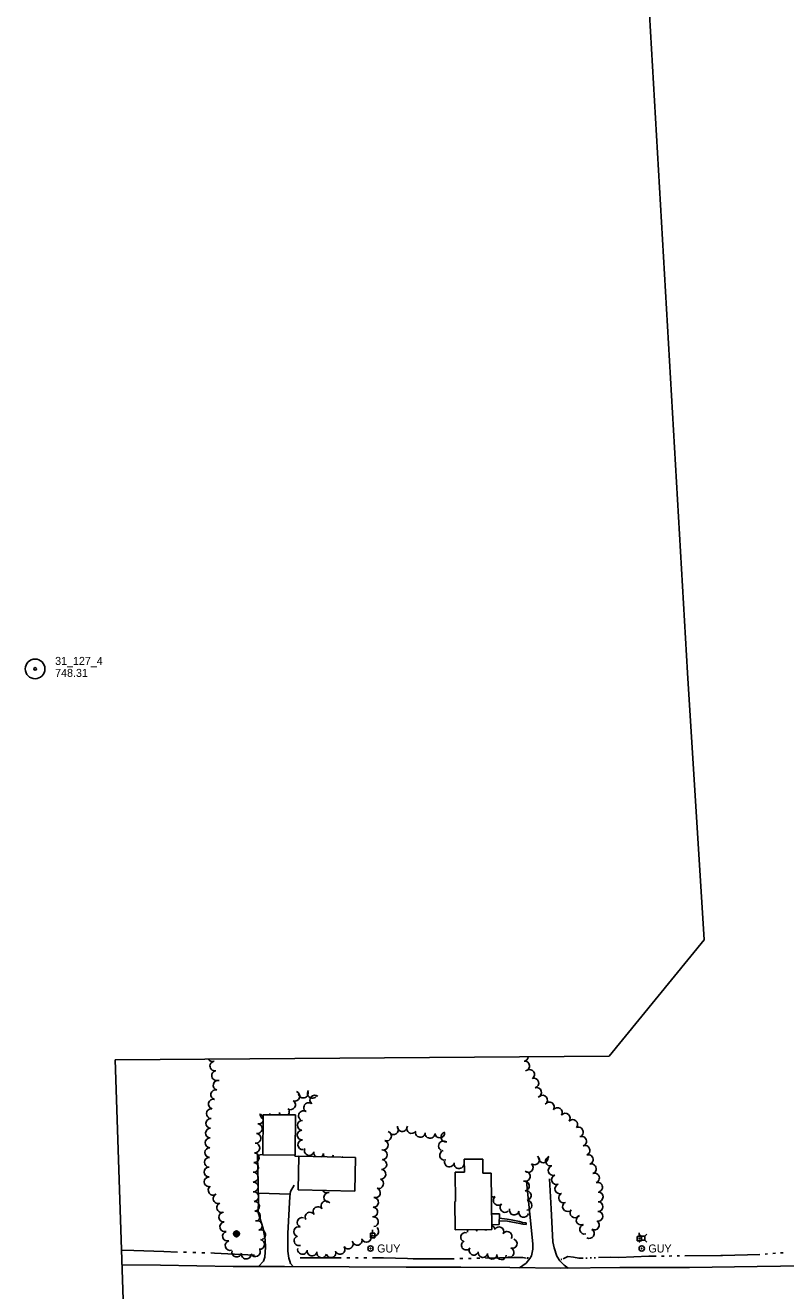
# Model space of a CAD drawing. Extents: x 589250 to 1188077, y 162953 to 363065.
# Drawn here: x 593418 to 593989, y 170392 to 171341 of the extents above; entities that cross this region are included whole.
import ezdxf

# ---------------------------------------------------------------- set-up
doc = ezdxf.new("R2010")
doc.units = 0
for name, color, linetype in [('E_BLD', 7, 'Continuous'), ('E_BLD_HvyDash', 7, 'Continuous'), ('E_DRN', 7, 'Continuous'), ('E_DWY', 7, 'Continuous'), ('E_LAND_TreeLine_P', 7, 'Continuous'), ('E_MAP_Limits', 7, 'Continuous'), ('E_MAP_PassPoints', 7, 'Continuous'), ('E_MISCPROP', 7, 'Continuous'), ('E_PATH_Sidewalk', 7, 'Continuous'), ('E_RDWY', 7, 'Continuous'), ('E_UTL_AG_Bold', 7, 'Continuous'), ('E_UTL_EGuyWire', 7, 'Continuous'), ('E_UTL_EPowerPole', 7, 'Continuous'), ('E_WTR_FlowLine', 7, 'Continuous')]:
    doc.layers.add(name, color=color, linetype=linetype)

msp = doc.modelspace()

# ---------------------------------------------------------------- linework, layer by layer
at = {"layer": 'E_BLD'}
for p, q in [((593596.59, 170524.31), (593596.3, 170494.1)), ((593620.91, 170524.08), (593596.59, 170524.31)), ((593620.62, 170493.87), (593620.91, 170524.08)), ((593596.3, 170494.1), (593620.62, 170493.87)), ((593622.87, 170467.85), (593623.47, 170493.12)), ((593623.47, 170493.12), (593665.84, 170492.11)), ((593665.84, 170492.11), (593665.24, 170466.84)), ((593747.47, 170490.87), (593761.25, 170491.02)), ((593747.58, 170481.31), (593747.47, 170490.87)), ((593761.25, 170491.02), (593761.36, 170480.45)), ((593740.62, 170481.23), (593747.58, 170481.31)), ((593740.87, 170459.14), (593740.62, 170481.23)), ((593761.36, 170480.45), (593767.6, 170480.52)), ((593767.6, 170480.52), (593768.07, 170438.24)), ((593665.24, 170466.84), (593622.87, 170467.85)), ((593740.48, 170459.14), (593740.87, 170459.14)), ((593740.71, 170437.93), (593740.48, 170459.14)), ((593768.07, 170438.24), (593740.71, 170437.93))]:
    msp.add_line(p, q, dxfattribs=at)
at = {"layer": 'E_BLD_HvyDash'}
for p, q in [((593773.77, 170449.92), (593767.94, 170450.05)), ((593773.65, 170441.94), (593773.77, 170449.92)), ((593768.03, 170441.78), (593773.65, 170441.94))]:
    msp.add_line(p, q, dxfattribs=at)
at = {"layer": 'E_DRN'}
for centre, radius, start, end in [((593794.38, 170417.05), 0.781, 280.48427, 26.74447), ((593820.6, 170415.98), 0.391, 153.61437, 259.87457)]:
    msp.add_arc(centre, radius, start, end, dxfattribs=at)
at = {"layer": 'E_DWY'}
for p, q in [((593592.33, 170494.01), (593596.3, 170494.4)), ((593593.14, 170460.32), (593592.33, 170494.01)), ((593620.11, 170493.87), (593620.58, 170493.26)), ((593620.58, 170493.26), (593623.47, 170493.01)), ((593796.71, 170449.6), (593794.02, 170474.12)), ((593811.44, 170476.21), (593812.67, 170453.71)), ((593593.02, 170465.45), (593616.88, 170464.81)), ((593617.17, 170466.68), (593616.62, 170463.05)), ((593619.81, 170471.44), (593617.17, 170466.68)), ((593592.89, 170450.95), (593593.14, 170460.32)), ((593616.62, 170463.05), (593615.17, 170435.08)), ((593596.56, 170438.94), (593592.89, 170450.95)), ((593798.96, 170427.37), (593796.71, 170449.6)), ((593812.67, 170453.71), (593813.91, 170428.89)), ((593597.99, 170430.55), (593596.56, 170438.94)), ((593615.17, 170435.08), (593615.07, 170421.94)), ((593598.42, 170424.96), (593597.99, 170430.55)), ((593798.97, 170423.41), (593798.96, 170427.37)), ((593813.91, 170428.89), (593814.79, 170424.39)), ((593596.78, 170414.33), (593597.89, 170417.55)), ((593597.89, 170417.55), (593598.42, 170424.96)), ((593615.07, 170421.94), (593615.78, 170416.63)), ((593615.78, 170416.63), (593616.49, 170414.53)), ((593793.92, 170412.94), (593796.67, 170416.43)), ((593796.67, 170416.43), (593797.83, 170418.47)), ((593797.83, 170418.47), (593798.97, 170423.41)), ((593814.79, 170424.39), (593816.85, 170418.3)), ((593816.85, 170418.3), (593819.18, 170414.68)), ((593593.15, 170410.46), (593596.78, 170414.33)), ((593616.49, 170414.53), (593617.2, 170412.58)), ((593617.2, 170412.58), (593619.02, 170410.38)), ((593788.85, 170409.54), (593793.92, 170412.94)), ((593819.18, 170414.68), (593822.38, 170411.49)), ((593822.38, 170411.49), (593825.44, 170409.26))]:
    msp.add_line(p, q, dxfattribs=at)
at = {"layer": 'E_LAND_TreeLine_P'}
for centre, radius, start, end in [((593558.53, 170567.82), 3.65, 210.62005, 292.17055), ((593560.34, 170560.77), 3.65, 100.38339, 280.38339), ((593791.82, 170568.04), 3.65, 277.67528, 353.96501), ((593792.8, 170560.8), 3.65, 277.67528, 97.67528), ((593561.66, 170553.58), 3.65, 100.38339, 280.38339), ((593562.76, 170546.4), 3.65, 75.64496, 255.64496), ((593796.44, 170554.51), 3.65, 301.78692, 121.78692), ((593799.64, 170548), 3.65, 286.68378, 106.68378), ((593560.94, 170539.31), 3.65, 75.64496, 255.64496), ((593620.34, 170538.16), 3.65, 251.74447, 71.74447), ((593626.74, 170540.47), 3.65, 191.48935, 11.48935), ((593633.51, 170540.23), 3.65, 142.02219, 322.02219), ((593801.74, 170541), 3.65, 286.68378, 106.68378), ((593559.13, 170532.23), 3.65, 75.64496, 255.64496), ((593617.15, 170531.65), 3.65, 236.48935, 56.48935), ((593630.72, 170529.65), 3.65, 57.15555, 237.15555), ((593635.34, 170535.32), 3.65, 50.07851, 230.07851), ((593806.14, 170535.2), 3.65, 308.5469, 128.5469), ((593811.24, 170530.07), 3.65, 325.40159, 145.40159), ((593557.36, 170517.8), 3.65, 87.6533, 267.6533), ((593557.66, 170525.1), 3.65, 87.6533, 267.6533), ((593593.3, 170521.07), 3.65, 26.57538, 79.39512), ((593597.95, 170524.69), 3.65, 186.25188, 247.51465), ((593597.95, 170524.69), 3.65, 353.28171, 6.25188), ((593605.22, 170525.49), 3.65, 186.25188, 199.59145), ((593605.22, 170525.49), 3.65, 339.31894, 6.25188), ((593612.45, 170526.47), 3.65, 196.12482, 218.57161), ((593612.45, 170526.47), 3.65, 320.33879, 16.12482), ((593626.76, 170523.51), 3.65, 57.15555, 237.15555), ((593817.26, 170525.92), 3.65, 325.40159, 145.40159), ((593823.22, 170521.7), 3.65, 320.14916, 140.14916), ((593828.83, 170517.01), 3.65, 320.14916, 140.14916), ((593557.06, 170510.49), 3.65, 87.6533, 267.6533), ((593592.12, 170513.86), 3.65, 263.0544, 83.0544), ((593593.3, 170521.07), 3.65, 259.39512, 332.33501), ((593625.78, 170509.04), 3.65, 93.87081, 273.87081), ((593625.93, 170516.34), 3.65, 86.48803, 266.48803), ((593689.16, 170508.32), 3.65, 250.5256, 70.5256), ((593694.37, 170513.03), 3.65, 213.29076, 33.29076), ((593700.88, 170515.3), 3.65, 172.74801, 352.74801), ((593707.97, 170513.89), 3.65, 149.21566, 329.21566), ((593714.52, 170511), 3.65, 174.46883, 354.46883), ((593733.67, 170507.57), 3.65, 101.48935, 281.48935), ((593832.97, 170511.29), 3.65, 290.08317, 110.08317), ((593556.76, 170503.19), 3.65, 87.6533, 267.6533), ((593590.46, 170499.34), 3.65, 265.86339, 85.86339), ((593591.23, 170506.61), 3.65, 263.0544, 83.0544), ((593626.27, 170501.75), 3.65, 93.87081, 273.87081), ((593686.72, 170501.42), 3.65, 250.5256, 70.5256), ((593721.8, 170510.29), 3.65, 174.46883, 354.46883), ((593729.08, 170510.56), 3.65, 184.75334, 4.75334), ((593731.8, 170500.89), 3.65, 62.10693, 242.10693), ((593835.48, 170504.43), 3.65, 290.08317, 110.08317), ((593556.18, 170488.58), 3.65, 87.74277, 267.74277), ((593556.47, 170495.88), 3.65, 87.74277, 267.74277), ((593589.93, 170492.05), 3.65, 265.86339, 85.86339), ((593631.15, 170497.39), 3.65, 153.61437, 333.61437), ((593638.24, 170495.8), 3.65, 170.49063, 234.65458), ((593638.24, 170495.8), 3.65, 302.62182, 350.49063), ((593645.45, 170494.59), 3.65, 170.49063, 211.71243), ((593645.45, 170494.59), 3.65, 325.56397, 350.49063), ((593652.66, 170493.4), 3.65, 170.7171, 194.16346), ((593652.66, 170493.4), 3.65, 343.11294, 350.7171), ((593686.07, 170494.23), 3.65, 270.17942, 90.17942), ((593732.63, 170493.92), 3.65, 104.21566, 284.21566), ((593800.14, 170490.33), 3.65, 230.37385, 50.37385), ((593806.8, 170491.94), 3.65, 182.30052, 2.30052), ((593812.1, 170489.47), 3.65, 105.82167, 285.82167), ((593837.99, 170497.56), 3.65, 290.08317, 110.08317), ((593840.44, 170490.67), 3.65, 288.61437, 108.61437), ((593556, 170481.27), 3.65, 90.17942, 270.17942), ((593589.4, 170484.76), 3.65, 265.86339, 85.86339), ((593684.94, 170479.66), 3.65, 264.60722, 84.60722), ((593685.63, 170486.94), 3.65, 264.60722, 84.60722), ((593736.28, 170488.82), 3.65, 169.68794, 349.68794), ((593743.47, 170487.51), 3.65, 169.68794, 349.68794), ((593750.7, 170486.42), 3.65, 171.56377, 210.00969), ((593795.48, 170484.7), 3.65, 230.37385, 50.37385), ((593814.12, 170482.44), 3.65, 109.92626, 289.92626), ((593842.78, 170483.75), 3.65, 288.61437, 108.61437), ((593556.03, 170473.96), 3.65, 90.17942, 270.17942), ((593589.2, 170477.46), 3.65, 270.17942, 90.17942), ((593589.22, 170470.15), 3.65, 270.17942, 90.17942), ((593683.27, 170472.6), 3.65, 250.3242, 70.3242), ((593792.48, 170470.77), 3.65, 281.48935, 101.48935), ((593793.26, 170478.02), 3.65, 262.82704, 82.82704), ((593816.61, 170475.57), 3.65, 109.92626, 289.92626), ((593845.11, 170476.82), 3.65, 288.61437, 108.61437), ((593847.45, 170469.89), 3.65, 288.61437, 108.61437), ((593559.06, 170467.61), 3.65, 125.00391, 305.00391), ((593562.83, 170461.39), 3.65, 111.98083, 291.98083), ((593589.51, 170462.85), 3.65, 275.02342, 95.02342), ((593644.35, 170469.37), 3.65, 212.37985, 287.28215), ((593645.8, 170462.3), 3.65, 87.16663, 267.16663), ((593680.81, 170465.72), 3.65, 250.3242, 70.3242), ((593793.94, 170463.6), 3.65, 281.48935, 101.48935), ((593819.1, 170468.7), 3.65, 109.92626, 289.92626), ((593821.89, 170461.94), 3.65, 112.55955, 292.55955), ((593847.88, 170462.66), 3.65, 269.22458, 89.22458), ((593565.56, 170454.61), 3.65, 111.98083, 291.98083), ((593590.15, 170455.57), 3.65, 275.02342, 95.02342), ((593637.76, 170451.66), 3.65, 35.88611, 215.88611), ((593643.68, 170455.95), 3.65, 35.88611, 215.88611), ((593678.84, 170451.31), 3.65, 265.13697, 85.13697), ((593679.46, 170458.59), 3.65, 265.13697, 85.13697), ((593769.17, 170466.19), 3.65, 247.86032, 294.52051), ((593772.89, 170460), 3.65, 133.71062, 313.71062), ((593777.94, 170454.72), 3.65, 133.71062, 313.71062), ((593794.51, 170456.37), 3.65, 267.45311, 87.45311), ((593824.87, 170455.32), 3.65, 139.94306, 319.94306), ((593847.78, 170455.35), 3.65, 269.22458, 89.22458), ((593567, 170447.51), 3.65, 95.70696, 275.70696), ((593590.79, 170448.28), 3.65, 275.02342, 95.02342), ((593592.21, 170441.17), 3.65, 289.83324, 109.83324), ((593625.72, 170443.5), 3.65, 69.85628, 249.85628), ((593631.75, 170447.51), 3.65, 31.9389, 211.9389), ((593679.31, 170444.03), 3.65, 275.07851, 95.07851), ((593784.9, 170452.73), 3.65, 166.14318, 346.14318), ((593792, 170450.98), 3.65, 166.14318, 346.14318), ((593830.47, 170450.62), 3.65, 139.94306, 319.94306), ((593835.11, 170445.22), 3.65, 111.55004, 291.55004), ((593844.98, 170441.47), 3.65, 239.4797, 59.4797), ((593847.68, 170448.05), 3.65, 269.22458, 89.22458), ((593567.8, 170440.25), 3.65, 105.77223, 285.77223), ((593569.79, 170433.21), 3.65, 105.77223, 285.77223), ((593594.69, 170434.3), 3.65, 289.83324, 109.83324), ((593623.2, 170436.64), 3.65, 69.85628, 249.85628), ((593679.56, 170436.88), 3.65, 227.90573, 47.90573), ((593748.27, 170432.4), 3.52, 75.248, 255.248), ((593753.29, 170436.55), 3.52, 155.03675, 185.37385), ((593753.29, 170436.55), 3.52, 5.37385, 26.23806), ((593760.29, 170437.21), 3.52, 165.15537, 185.37385), ((593766.92, 170437.92), 3.52, 175.65971, 186.18843), ((593760.29, 170437.21), 3.52, 5.37385, 16.11944), ((593766.92, 170437.92), 3.52, 6.18843, 71.54959), ((593773.54, 170436.7), 3.52, 332.10693, 152.10693), ((593779.63, 170433.19), 3.52, 328.57192, 148.57192), ((593837.73, 170438.41), 3.65, 104.21566, 284.21566), ((593841.27, 170435.17), 3.65, 239.4797, 59.4797), ((593571.78, 170426.18), 3.65, 105.77223, 285.77223), ((593594.04, 170427.09), 3.65, 262.32611, 82.32611), ((593623.45, 170429.72), 3.65, 107.99831, 287.99831), ((593660.41, 170427.33), 3.65, 213.29076, 33.29076), ((593667.12, 170430.05), 3.65, 196.68378, 16.68378), ((593674.07, 170432.3), 3.65, 201.98083, 21.98083), ((593748.8, 170426.35), 3.52, 140.37385, 320.37385), ((593783.49, 170427.63), 3.52, 251.00041, 71.00041), ((593576.81, 170421.27), 3.65, 166.9389, 346.9389), ((593583.95, 170419.74), 3.65, 174.46883, 354.46883), ((593590.77, 170421.48), 3.65, 206.74447, 26.74447), ((593626.09, 170423.22), 3.65, 170.45184, 350.45184), ((593633.3, 170422), 3.65, 170.45184, 350.45184), ((593640.48, 170420.65), 3.65, 166.14318, 346.14318), ((593647.48, 170420.71), 3.65, 199.9783, 19.9783), ((593654.3, 170423.31), 3.65, 213.29076, 33.29076), ((593754.67, 170422.48), 3.52, 147.27418, 327.27418), ((593761.42, 170420.76), 3.52, 169.22536, 349.22536), ((593768.35, 170419.58), 3.52, 176.0938, 356.0938), ((593775.37, 170419.1), 3.52, 176.0938, 356.0938), ((593781.2, 170420.97), 3.52, 251.00041, 71.00041)]:
    msp.add_arc(centre, radius, start, end, dxfattribs=at)
at = {"layer": 'E_MAP_Limits'}
for p, q in [((593914.91, 170855.75), (593880.25, 171456.06)), ((593927.49, 170655.35), (593914.91, 170855.75)), ((593856.11, 170568.09), (593927.49, 170655.35)), ((593485.69, 170565.46), (593856.11, 170568.09)), ((593496.33, 170239.23), (593485.69, 170565.46))]:
    msp.add_line(p, q, dxfattribs=at)
at = {"layer": 'E_MAP_PassPoints'}
for radius in [7.38, 7.38, 0.945, 0.945]:
    msp.add_circle((593425.57, 170858.64), radius, dxfattribs=at)
at = {"layer": 'E_MISCPROP'}
for radius in [2.23, 1.67, 1.12, 0.558]:
    msp.add_circle((593576.62, 170434.92), radius, dxfattribs=at)
at = {"layer": 'E_PATH_Sidewalk'}
for p, q in [((593773.69, 170444.8), (593779.81, 170444.52)), ((593773.72, 170446.61), (593779.66, 170446.03)), ((593779.66, 170446.03), (593782.52, 170445.44)), ((593782.52, 170445.44), (593788.85, 170444.1)), ((593779.81, 170444.52), (593783.73, 170443.78)), ((593783.73, 170443.78), (593787.95, 170442.89)), ((593787.95, 170442.89), (593791.26, 170442.15)), ((593788.85, 170444.1), (593791.11, 170443.5)), ((593791.11, 170443.5), (593793.97, 170443.21)), ((593791.26, 170442.15), (593793.97, 170441.86)), ((593793.97, 170443.21), (593793.97, 170441.86))]:
    msp.add_line(p, q, dxfattribs=at)
at = {"layer": 'E_RDWY'}
for p, q in [((593490.7, 170411.78), (593519.56, 170411.41)), ((593519.56, 170411.41), (593573.99, 170410.53)), ((593573.99, 170410.53), (593612.72, 170410.39)), ((593612.72, 170410.39), (593661.14, 170410.28)), ((593661.14, 170410.28), (593703.79, 170409.89)), ((593703.79, 170409.89), (593744.88, 170410.02)), ((593744.88, 170410.02), (593781.51, 170409.61)), ((593781.51, 170409.61), (593819.98, 170409.21)), ((593819.98, 170409.21), (593864.16, 170409.61)), ((593916.35, 170409.77), (593864.16, 170409.61)), ((593967.14, 170410.4), (593916.35, 170409.77)), ((594002.09, 170410.98), (593967.14, 170410.4))]:
    msp.add_line(p, q, dxfattribs=at)
at = {"layer": 'E_UTL_AG_Bold'}
for points in [[(593880.04, 170433.12), (593878.44, 170434.71)], [(593880.04, 170430.31), (593878.44, 170428.71)], [(593882.85, 170433.12), (593884.44, 170434.71)], [(593882.85, 170430.31), (593884.44, 170428.71)]]:
    msp.add_lwpolyline(points, dxfattribs=at)
msp.add_lwpolyline([(593880.04, 170430.31), (593882.85, 170430.31), (593882.85, 170433.12), (593880.04, 170433.12)], close=True, dxfattribs=at)
at = {"layer": 'E_UTL_EGuyWire'}
for centre, radius in [((593677.12, 170423.95), 2), ((593880.52, 170423.95), 2), ((593677.12, 170423.95), 0.25), ((593880.52, 170423.95), 0.25)]:
    msp.add_circle(centre, radius, dxfattribs=at)
at = {"layer": 'E_UTL_EPowerPole'}
for points in [[(593680.34, 170435.41), (593676.99, 170435.41)], [(593676.99, 170435.41), (593676.99, 170432.05)], [(593678.66, 170435.41), (593678.66, 170438.05)], [(593680.34, 170432.05), (593680.34, 170435.41)], [(593878.74, 170433.01), (593878.74, 170435.65)], [(593676.99, 170432.05), (593680.34, 170432.05)], [(593880.42, 170433.01), (593877.06, 170433.01)], [(593877.06, 170433.01), (593877.06, 170429.65)], [(593877.06, 170429.65), (593880.42, 170429.65)], [(593880.42, 170429.65), (593880.42, 170433.01)]]:
    msp.add_lwpolyline(points, dxfattribs=at)
for centre in [(593678.69, 170433.73), (593878.77, 170431.33)]:
    msp.add_circle(centre, 0.217, dxfattribs=at)
at = {"layer": 'E_WTR_FlowLine'}
for p, q in [((593499.59, 170422.38), (593490.35, 170422.7)), ((593522.06, 170421.61), (593499.59, 170422.38)), ((593532.41, 170421.31), (593522.06, 170421.61)), ((593539.21, 170421.12), (593536.94, 170421.19)), ((593546, 170420.93), (593543.73, 170420.99)), ((593552.79, 170420.74), (593550.53, 170420.8)), ((593560.21, 170420.52), (593557.32, 170420.61)), ((593590.12, 170419.01), (593560.21, 170420.52)), ((593624.45, 170416.93), (593634.52, 170416.83)), ((593634.52, 170416.83), (593655.18, 170416.89)), ((593659.42, 170416.9), (593661.54, 170416.89)), ((593665.78, 170416.89), (593667.9, 170416.88)), ((593672.14, 170416.87), (593674.26, 170416.87)), ((593678.5, 170416.86), (593686.94, 170416.85)), ((593686.94, 170416.85), (593704.84, 170416.35)), ((593704.84, 170416.35), (593709.22, 170416.31)), ((593709.23, 170416.31), (593728.19, 170416.14)), ((593728.19, 170416.14), (593739.96, 170416.32)), ((593744.2, 170416.39), (593746.32, 170416.42)), ((593750.55, 170416.49), (593750.98, 170416.49)), ((593750.98, 170416.49), (593752.67, 170416.53)), ((593756.91, 170416.63), (593759.03, 170416.69)), ((593763.26, 170416.79), (593784.39, 170417.3)), ((593784.39, 170417.3), (593788.16, 170417.31)), ((593788.16, 170417.31), (593791.24, 170417.32)), ((593791.24, 170417.32), (593792.64, 170416.9)), ((593792.64, 170416.9), (593793.9, 170416.63)), ((593821.72, 170416.29), (593825.21, 170417.84)), ((593825.21, 170417.84), (593829.26, 170417.44)), ((593829.26, 170417.44), (593833.46, 170416.61)), ((593833.46, 170416.61), (593836.53, 170416.7)), ((593838.63, 170416.77), (593839.68, 170416.8)), ((593841.79, 170416.86), (593842.84, 170416.9)), ((593844.94, 170416.97), (593845.99, 170417)), ((593848.09, 170417.08), (593856.95, 170417.38)), ((593856.95, 170417.38), (593863.32, 170417.29)), ((593863.32, 170417.29), (593885.75, 170418.1)), ((593885.75, 170418.1), (593891.47, 170418.17)), ((593895.36, 170418.23), (593897.3, 170418.25)), ((593901.18, 170418.3), (593903.13, 170418.33)), ((593907.01, 170418.38), (593908.95, 170418.41)), ((593912.84, 170418.45), (593939.86, 170418.75)), ((593939.86, 170418.75), (593941, 170418.78)), ((593941, 170418.78), (593969.16, 170419.52)), ((593973.04, 170419.7), (593974.97, 170419.86)), ((593978.84, 170420.18), (593980.78, 170420.34)), ((593984.65, 170420.65), (593986.59, 170420.81))]:
    msp.add_line(p, q, dxfattribs=at)

# ---------------------------------------------------------------- texts
at = {"layer": 'E_MAP_PassPoints'}
for s, p in [('31_127_4', (593440.57, 170861.63)), ('31_127_4', (593440.57, 170861.63)), ('748.31', (593440.57, 170852.63)), ('748.31', (593440.57, 170852.63))]:
    msp.add_text(s, height=6, dxfattribs=at).set_placement(p)
at = {"layer": 'E_UTL_EGuyWire'}
for p in [(593682.12, 170420.95), (593885.52, 170420.95)]:
    msp.add_text('GUY', height=6, dxfattribs=at).set_placement(p)

doc.saveas('drawing.dxf')
